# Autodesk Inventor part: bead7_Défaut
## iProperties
Shininess: 64.0
Length Units: 11269
Angle Units: 11279
Time Units: 11290
Mass Units: 11283
Length Display Precision: 3
Angle Display Precision: 2
Compacted: True
Part Number: bead7_Défaut
Document SubType Name: Modeling
Created: 2006-01
Material: Par défaut
Designer: Fricot
Density: 0.0
Volumn: 0.0
Area: 0.0
PropertySet Name: Model Information
Control State: 0
Master: False
Checked Out: False
Author: Fricot
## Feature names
1. Base1
